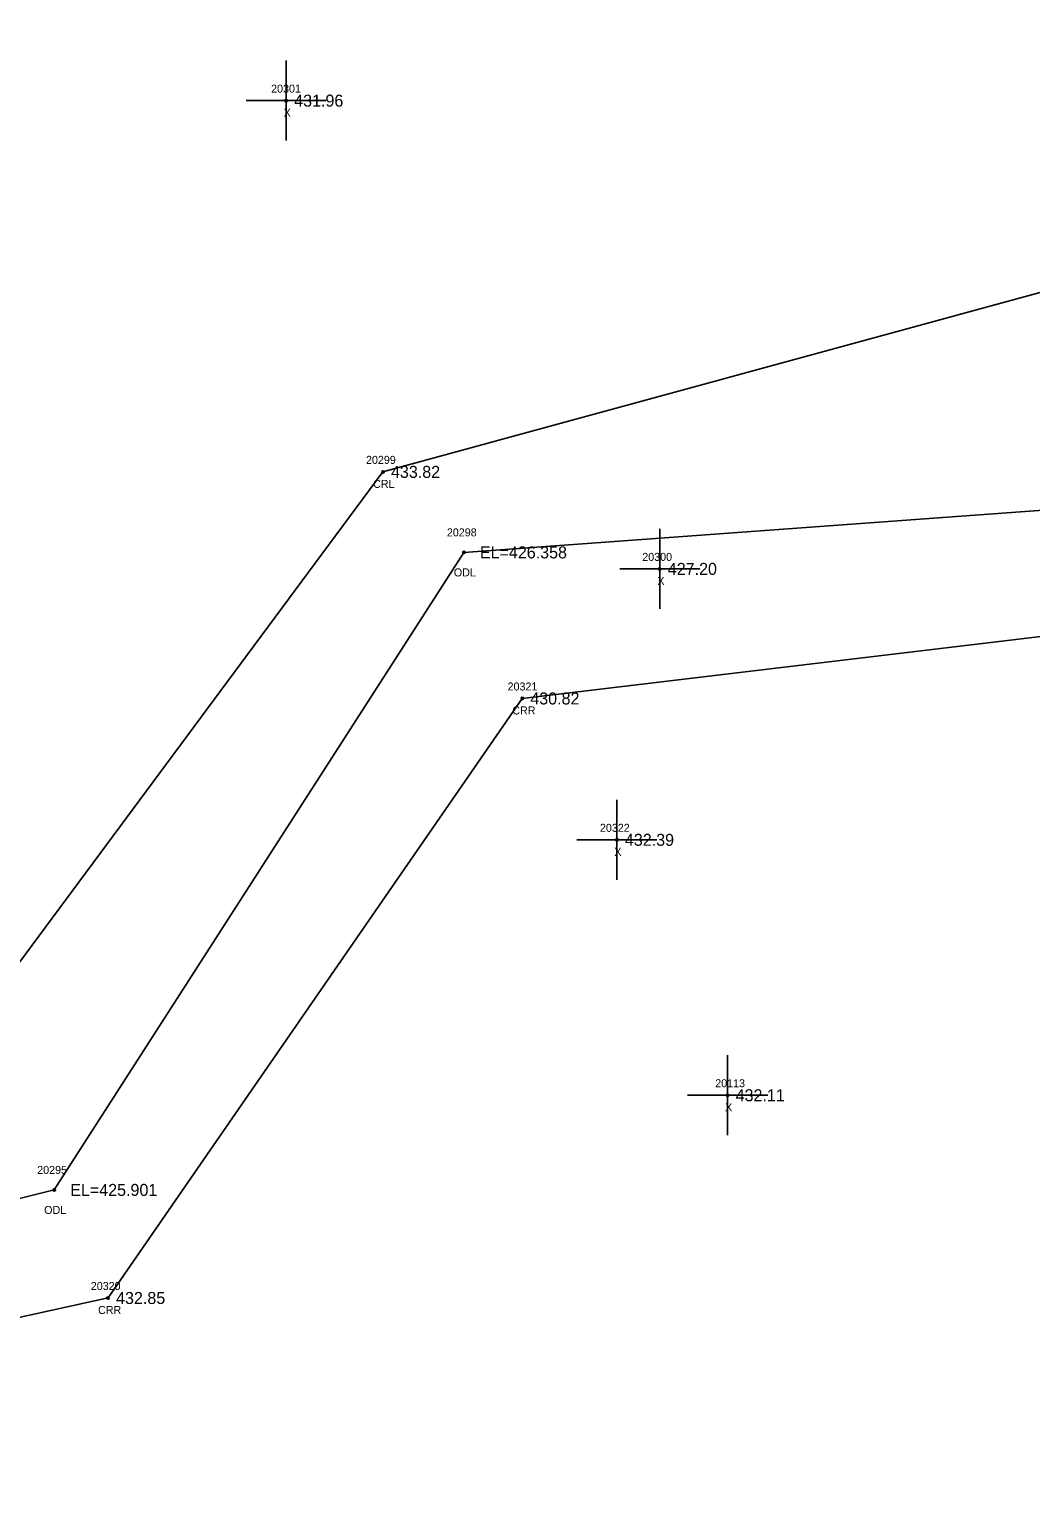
# Model space of a CAD drawing. Extents: x 1755707 to 1756750, y 975854 to 977363.
# Drawn here: x 1755979.4 to 1756104.5, y 976425.4 to 976608 of the extents above; entities that cross this region are included whole.
import ezdxf

# ---------------------------------------------------------------- set-up
doc = ezdxf.new("R2010")
doc.units = 0
for name, color, linetype in [('RD_EX_H2O', 7, 'Continuous'), ('RD_EX_H2O_txCode', 7, 'Continuous'), ('RD_EX_Misc', 7, 'Continuous'), ('RD_EX_Misc_txCode', 7, 'Continuous'), ('RD_EX_TX_H2O_ELEV', 7, 'Continuous'), ('RD_EX_TX_Misc_ELEV', 7, 'Continuous'), ('RD_SMD_Locator', 7, 'Continuous')]:
    doc.layers.add(name, color=color, linetype=linetype)

msp = doc.modelspace()

# ---------------------------------------------------------------- linework, layer by layer
at = {"layer": 'RD_EX_H2O'}
for points in [[(1755737.32, 976440.59), (1755791.96, 976465.24), (1755883.28, 976455.13), (1755971.27, 976482.19), (1756023.59, 976552.72), (1756109.16, 976576.08), (1756159.34, 976597.67), (1756188.28, 976619.95), (1756188.72, 976628.61)], [(1755742.06, 976428.66), (1755806.09, 976451.93), (1755887.6, 976439.2), (1755982.53, 976463.01), (1756033.69, 976542.66), (1756128.83, 976549.6), (1756169.54, 976582.49), (1756188.08, 976603.54), (1756206.03, 976613.84), (1756222.85, 976613.36), (1756242.15, 976615.93), (1756317.48, 976609.64), (1756394.89, 976590.11), (1756422.33, 976593.66), (1756518.23, 976582.93), (1756609.24, 976524.24), (1756704.51, 976490.62)], [(1755755.31, 976405), (1755806.36, 976424.52), (1755883.37, 976426.21), (1755989.26, 976449.51), (1756040.99, 976524.41), (1756109.22, 976532.55), (1756144.58, 976545.85), (1756166.57, 976563.07), (1756180.02, 976571), (1756216.66, 976584.76), (1756224.04, 976598.1), (1756313.82, 976585.45), (1756418.42, 976576.49), (1756511.71, 976558.86), (1756604.42, 976511.73), (1756702.67, 976481.09)]]:
    msp.add_lwpolyline(points, dxfattribs=at)
at = {"layer": 'RD_EX_Misc'}
for p, q in [((1756011.5, 976594.1), (1756011.5, 976604.1)), ((1756006.5, 976599.1), (1756016.5, 976599.1)), ((1756058.16, 976535.6), (1756058.16, 976545.6)), ((1756053.16, 976540.6), (1756063.16, 976540.6)), ((1756052.8, 976501.75), (1756052.8, 976511.75)), ((1756047.8, 976506.75), (1756057.8, 976506.75)), ((1756066.63, 976469.84), (1756066.63, 976479.84)), ((1756061.63, 976474.84), (1756071.63, 976474.84))]:
    msp.add_line(p, q, dxfattribs=at)
at = {"layer": 'RD_SMD_Locator'}
for centre in [(1756011.5, 976599.1), (1756023.59, 976552.72), (1756033.69, 976542.66), (1756058.16, 976540.6), (1756040.99, 976524.41), (1756052.8, 976506.75), (1756066.63, 976474.84), (1755982.53, 976463.01), (1755989.26, 976449.51)]:
    msp.add_circle(centre, 0.15, dxfattribs=at)

# ---------------------------------------------------------------- texts
at = {"layer": 'RD_EX_H2O_txCode'}
for s, p in [('20299', (1756021.47, 976553.72)), ('CRL', (1756022.36, 976550.72)), ('20298', (1756031.57, 976544.66)), ('ODL', (1756032.44, 976539.66)), ('20321', (1756039.15, 976525.41)), ('CRR', (1756039.74, 976522.41)), ('20295', (1755980.41, 976465.01)), ('ODL', (1755981.28, 976460.01)), ('20320', (1755987.1, 976450.51)), ('CRR', (1755988.01, 976447.51))]:
    msp.add_text(s, height=1, dxfattribs=at).set_placement(p)
at = {"layer": 'RD_EX_Misc_txCode'}
for s, p in [('20301', (1756009.62, 976600.1)), ('X', (1756011.18, 976597.1)), ('20300', (1756055.97, 976541.6)), ('X', (1756057.85, 976538.6)), ('20322', (1756050.68, 976507.75)), ('X', (1756052.48, 976504.75)), ('20113', (1756065.08, 976475.84)), ('X', (1756066.31, 976472.84))]:
    msp.add_text(s, height=1, dxfattribs=at).set_placement(p)
at = {"layer": 'RD_EX_TX_H2O_ELEV'}
for s, p in [('433.82', (1756024.59, 976551.97)), ('EL=426.358', (1756035.69, 976541.91)), ('430.82', (1756041.99, 976523.66)), ('EL=425.901', (1755984.53, 976462.26)), ('432.85', (1755990.26, 976448.76))]:
    msp.add_text(s, height=1.5, dxfattribs=at).set_placement(p)
at = {"layer": 'RD_EX_TX_Misc_ELEV'}
for s, p in [('431.96', (1756012.5, 976598.35)), ('427.20', (1756059.16, 976539.85)), ('432.39', (1756053.8, 976506)), ('432.11', (1756067.63, 976474.09))]:
    msp.add_text(s, height=1.5, dxfattribs=at).set_placement(p)

doc.saveas('drawing.dxf')
